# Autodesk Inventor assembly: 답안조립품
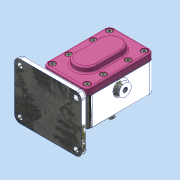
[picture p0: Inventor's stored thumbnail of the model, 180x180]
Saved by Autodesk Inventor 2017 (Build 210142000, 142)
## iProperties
Part Number: 답안조립품
Material: 일반
Document SubType Name: Assembly
Designer: MRC
Author: MRC
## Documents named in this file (11)
- C:\Users\MRC\Desktop\700407V1041\답안조립품.iam
- C:\Users\MRC\Desktop\700407V1041\본체.ipt
- C:\Users\MRC\Desktop\700407V1041\Ű 6 x 6 x 18.ipt
- C:\Users\MRC\Desktop\700407V1041\개스킷.ipt
- C:\Users\MRC\Desktop\700407V1041\메인축.ipt
- C:\Users\MRC\Desktop\700407V1041\베어링부시.ipt
- C:\Users\MRC\Desktop\700407V1041\볼트 M5.ipt
- C:\Users\MRC\Desktop\700407V1041\서브축.ipt
- C:\Users\MRC\Desktop\700407V1041\스퍼기어.ipt
- C:\Users\MRC\Desktop\700407V1041\오일 실 16 28 7.ipt
- C:\Users\MRC\Desktop\700407V1041\커버.ipt
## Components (3 placed, 2 different names)
1. Ű 6 x 6 x 18:1 — 각도:1
2. 개스킷:1
3. Ű 6 x 6 x 18:2 — 각도:2
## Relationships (2: Angle 2)
- 각도:1 [Angle]: Ű 6 x 6 x 18:1
- 각도:2 [Angle]: Ű 6 x 6 x 18:2
